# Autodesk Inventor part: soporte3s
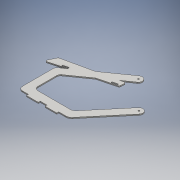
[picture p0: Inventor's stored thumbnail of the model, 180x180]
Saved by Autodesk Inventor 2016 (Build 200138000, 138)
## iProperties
Created: 2016-06
Part Number: soporte3s
Material: Genérico
Document SubType Name: Modeling
Designer: adm
Density: 1 g/cm^3
Appearance: Valor por defecto
Author: adm
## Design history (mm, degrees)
sketch "Boceto1"
  geometry: L1 (-161.273, -190.979)-(3.65, -190.979); L2 (-109.73, -230.979)-(-75.003, -230.979); L3 (-109.73, -230.979)-(-75.003, -230.979); L4 (-75.003, -230.979)-(-75.003, -240.979); L5 (-75.003, -230.979)-(-75.003, -240.979); L6 (-75.003, -240.979)-(-15.003, -240.979); L7 (-75.003, -240.979)-(-15.003, -240.979); L8 (-15.003, -240.979)-(-15.003, -230.979); L9 (-15.003, -240.979)-(-15.003, -230.979); L10 (-15.003, -230.979)-(22.302, -230.979); L11 (-109.73, -240.979)-(-109.73, -230.979); L12 (-181.273, -74.736)-(-181.273, -170.979); L13 (-221.273, -54.025)-(-221.273, -210.979); L14 (-169.73, -230.979)-(-169.73, -240.979); L15 (-169.73, -230.979)-(-169.73, -240.979); L16 (-109.73, -240.979)-(-109.73, -230.979); L17 (-109.73, -240.979)-(-109.73, -230.979); L18 (-169.73, -240.979)-(-109.73, -240.979); L19 (-169.73, -240.979)-(-109.73, -240.979); L20 (-201.273, -230.979)-(-169.73, -230.979); L21 (-169.73, -230.979)-(-169.73, -240.979); L22 (201.715, -33.835)-(45.284, -220.263); L23 (45.284, -220.263)-(201.715, -33.835); L24 (171.073, -8.123)-(26.631, -180.263); L25 (22.169, 69.365)-(1.485, 64.788); L26 (22.169, 69.365)-(1.485, 64.788); L27 (1.485, 64.788)-(55.109, 102.688); L28 (1.485, 64.788)-(55.109, 102.688); L29 (-70.881, 13.642)-(22.812, 38.289); L30 (-172.816, -58.403)-(-70.881, 13.642); L31 (-70.881, 13.642)-(22.812, 38.289); L32 (26.532, 42.84)-(27.743, 64.115); L33 (26.532, 42.84)-(27.743, 64.115); L34 (32.022, 135.353)-(-99.407, 42.463); L35 (32.022, 135.353)-(-99.407, 42.463); L36 (-99.407, 42.463)-(-226.174, 14.411); L37 (-99.407, 42.463)-(-253.277, 8.414); L38 (-183.373, -12.849)-(-184.899, -7.046); L39 (-181.273, -15.398)-(-212.816, -37.692); L40 (-211.978, -14.169)-(-210.451, -19.972); L41 (-183.373, -12.849)-(-210.451, -19.972); L42 (-210.451, -19.972)-(-183.373, -12.849); L43 (-211.978, -14.169)-(-184.899, -7.046); L44 (-269.159, -38.518)-(-181.273, -15.398); L45 (-256.687, 5.732)-(-274.921, -31.482); L46 (-184.899, -7.046)-(-211.978, -14.169); C1 r 3.25 at (186.394, -20.979); C2 r 3.75 at (186.394, -20.979); C3 r 3.25 at (43.566, 119.021); C4 r 3.75 at (43.566, 119.021); A1 r 20 centre (-161.273, -74.736) between (-172.816, -58.403) and (-181.273, -74.736); A2 r 30 centre (3.65, -160.979) between (3.65, -190.979) and (26.631, -180.263); A3 r 30 centre (3.65, -160.979) between (3.65, -190.979) and (26.631, -180.263); A4 r 30 centre (22.302, -200.979) between (22.302, -230.979) and (45.284, -220.263); A5 r 30 centre (22.302, -200.979) between (22.302, -230.979) and (45.284, -220.263); A6 r 20 centre (-161.273, -170.979) between (-181.273, -170.979) and (-161.273, -190.979); A7 r 20 centre (-201.273, -210.979) between (-221.273, -210.979) and (-201.273, -230.979); A8 r 20 centre (186.394, -20.979) between (201.715, -33.835) and (171.073, -8.123); A9 r 20 centre (43.566, 119.021) between (55.109, 102.688) and (32.022, 135.353); A10 r 5 centre (22.751, 64.399) between (27.743, 64.115) and (22.169, 69.365); A11 r 5 centre (22.751, 64.399) between (27.743, 64.115) and (21.183, 69.147); A12 r 5 centre (21.54, 43.125) between (22.812, 38.289) and (26.532, 42.84); A13 r 5 centre (21.54, 43.125) between (22.812, 38.289) and (26.532, 42.84); A14 r 20 centre (-201.273, -54.025) between (-212.816, -37.692) and (-221.273, -54.025); A15 r 5 centre (-270.431, -33.682) between (-274.921, -31.482) and (-269.159, -38.518); A16 r 5 centre (-252.197, 3.532) between (-253.277, 8.414) and (-256.687, 5.732); 7 further points
  constraints: 95 end point, 35 point on circle, 20 centre point, 14 tangent, 11 point on line, 8 coincident, 8 collinear, 6 perpendicular, 3 vertical, 2 horizontal, 2 parallel
  dimensions: "d0" = 40 distance between parallel lines of L12 L13; "d1" = 20 radius of A6; "d2" = 20 radius of A7; "d3" = 20 radius of A1; "d4" = 20 radius of A14; "d5" = 7.5 diameter of C2; "d6" = 160 distance of L34.end point (-255.628, 7.894); "d7" = 7.5 diameter of C4; "d8" = 5 radius of A16; "d9" = 5 radius of A15; "d12" = 10 distance between parallel lines of L18 L20; "d13" = 10 distance between parallel lines of L2 L6
extrude "Extrusión1" new body sketch "Boceto1" distance "d10" = 6; taper "d11" = 0 deg
sketch "Boceto2"
  geometry: L1 (-99.407, 42.463)-(-253.277, 8.414); L2 (-99.407, 42.463)-(-226.174, 14.411); L3 (-70.881, 13.642)-(22.812, 38.289); L4 (-172.816, -58.403)-(-70.881, 13.642); L5 (-70.881, 13.642)-(22.812, 38.289); L6 (-181.273, -74.736)-(-181.273, -170.979); L7 (-221.273, -54.025)-(-221.273, -210.979); L8 (-169.73, -230.979)-(-169.73, -238.979); L9 (-169.73, -230.979)-(-169.73, -238.979); L10 (-109.73, -230.979)-(-75.003, -230.979); L11 (-109.73, -230.979)-(-75.003, -230.979); L12 (-109.73, -238.979)-(-109.73, -230.979); L13 (-109.73, -238.979)-(-109.73, -230.979); L14 (-109.73, -238.979)-(-109.73, -230.979); L15 (-169.73, -238.979)-(-109.73, -238.979); L16 (-169.73, -238.979)-(-109.73, -238.979); L17 (-169.73, -230.979)-(-169.73, -238.979); L18 (-201.273, -230.979)-(-169.73, -230.979); L19 (-161.273, -190.979)-(3.65, -190.979); L20 (-75.003, -230.979)-(-75.003, -238.979); L21 (-75.003, -230.979)-(-75.003, -238.979); L22 (-75.003, -238.979)-(-15.003, -238.979); L23 (-75.003, -238.979)-(-15.003, -238.979); L24 (-15.003, -238.979)-(-15.003, -230.979); L25 (-15.003, -238.979)-(-15.003, -230.979); L26 (-15.003, -230.979)-(22.302, -230.979); L27 (-10.145, 32.721)-(-11.724, 38.721); L28 (-11.724, 38.721)-(-10.145, 32.721); L29 (32.022, 135.353)-(-99.407, 42.463); L30 (32.022, 135.353)-(-99.407, 42.463); L31 (-10.145, 32.721)-(16.933, 39.845); L32 (-11.724, 38.721)-(15.355, 45.845); L33 (15.355, 45.845)-(-11.724, 38.721); L34 (15.355, 45.845)-(16.933, 39.845); L35 (16.933, 39.845)-(15.355, 45.845); L36 (26.532, 42.84)-(27.743, 64.115); L37 (26.532, 42.84)-(27.743, 64.115); L38 (22.169, 69.365)-(1.485, 64.788); L39 (1.485, 64.788)-(55.109, 102.688); L40 (1.485, 64.788)-(55.109, 102.688); L41 (22.169, 69.365)-(1.485, 64.788); L42 (201.715, -33.835)-(45.284, -220.263); L43 (45.284, -220.263)-(201.715, -33.835); L44 (171.073, -8.123)-(26.631, -180.263); L45 (-183.373, -12.849)-(-184.899, -7.046); L46 (-181.273, -15.398)-(-212.816, -37.692); L47 (-211.978, -14.169)-(-210.451, -19.972); L48 (-183.373, -12.849)-(-210.451, -19.972); L49 (-210.451, -19.972)-(-183.373, -12.849); L50 (-211.978, -14.169)-(-184.899, -7.046); L51 (-184.899, -7.046)-(-211.978, -14.169); L52 (-269.159, -38.518)-(-181.273, -15.398); L53 (-256.687, 5.732)-(-274.921, -31.482); C1 r 3.25 at (186.394, -20.979); C2 r 3.75 at (186.394, -20.979); C3 r 3.25 at (43.566, 119.021); C4 r 3.75 at (43.566, 119.021); A1 r 20 centre (-161.273, -74.736) between (-172.816, -58.403) and (-181.273, -74.736); A2 r 20 centre (-161.273, -170.979) between (-181.273, -170.979) and (-161.273, -190.979); A3 r 20 centre (-201.273, -210.979) between (-221.273, -210.979) and (-201.273, -230.979); A4 r 30 centre (3.65, -160.979) between (3.65, -190.979) and (26.631, -180.263); A5 r 30 centre (3.65, -160.979) between (3.65, -190.979) and (26.631, -180.263); A6 r 30 centre (22.302, -200.979) between (22.302, -230.979) and (45.284, -220.263); A7 r 30 centre (22.302, -200.979) between (22.302, -230.979) and (45.284, -220.263); A8 r 5 centre (21.54, 43.125) between (22.812, 38.289) and (26.532, 42.84); A9 r 5 centre (21.54, 43.125) between (22.812, 38.289) and (26.532, 42.84); A10 r 5 centre (22.751, 64.399) between (27.743, 64.115) and (22.169, 69.365); A11 r 5 centre (22.751, 64.399) between (27.743, 64.115) and (21.183, 69.147); A12 r 20 centre (186.394, -20.979) between (201.715, -33.835) and (171.073, -8.123); A13 r 20 centre (43.566, 119.021) between (55.109, 102.688) and (32.022, 135.353); A14 r 5 centre (-270.431, -33.682) between (-274.921, -31.482) and (-269.159, -38.518); A15 r 5 centre (-252.197, 3.532) between (-253.277, 8.414) and (-256.687, 5.732); A16 r 20 centre (-201.273, -54.025) between (-212.816, -37.692) and (-221.273, -54.025); 7 further points
  constraints: 109 end point, 35 point on circle, 20 centre point, 14 tangent, 11 point on line, 9 collinear, 9 perpendicular, 8 coincident, 3 vertical, 2 horizontal, 2 parallel
  dimensions: "d14" = 40 distance between parallel lines of L6 L7; "d15" = 20 radius of A2; "d16" = 20 radius of A3; "d17" = 20 radius of A1; "d18" = 20 radius of A16; "d19" = 7.5 diameter of C2; "d20" = 160 distance of L1.start point (-255.628, 7.894); "d21" = 7.5 diameter of C4; "d22" = 5 radius of A15; "d23" = 5 radius of A14
extrude "Extrusión2" cut sketch "Boceto2" distance "d24" = 6; taper "d25" = 0 deg
node "Sólido1"
